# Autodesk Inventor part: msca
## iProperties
Shininess: 64.0
Length Units: 11269
Angle Units: 11279
Time Units: 11290
Mass Units: 11283
Length Display Precision: 3
Angle Display Precision: 2
Compacted: True
Part Number: msca
Document SubType Name: Modeling
Created: 2004-07
Designer: Peter
Manufacturer: Standard
Standards Organization: Custom
Density: 0.0
Volumn: 0.0
Area: 0.0
PropertySet Name: Model Information
Control State: 0
Master: False
Checked Out: False
Author: Peter
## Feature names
1. Extrusion1
